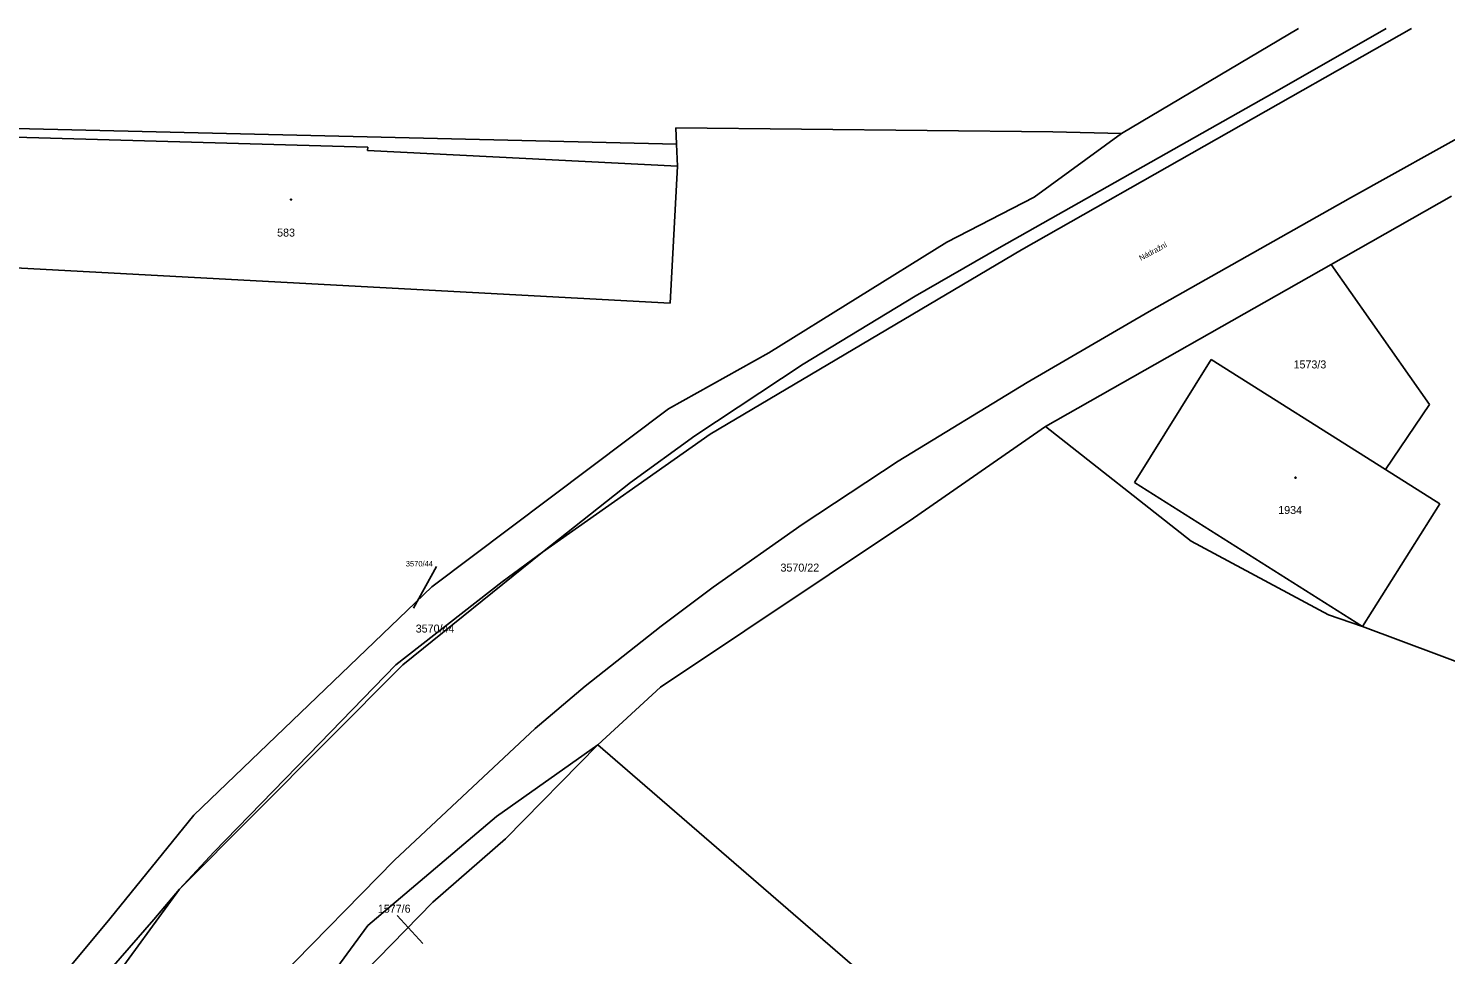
# Model space of a CAD drawing. Extents: x -866624 to -866276, y -1050208 to -1049940.
# Drawn here: x -866412 to -866323.5, y -1049998.1 to -1049940.2 of the extents above; entities that cross this region are included whole.
import ezdxf

# ---------------------------------------------------------------- set-up
doc = ezdxf.new("R2010")
doc.units = 0
for name, color, linetype in [('Default', 7, 'Continuous'), ('Hranice', 7, 'Continuous'), ('Hranice další', 7, 'Continuous'), ('Hranice-budov', 7, 'Continuous'), ('nazvy-ulic-tok', 7, 'Continuous'), ('Parcela-pozemkova', 7, 'Continuous'), ('Parcela-stavebni', 7, 'Continuous'), ('Parcelni-cisla-pomocna', 7, 'Continuous'), ('znacky-budov', 7, 'Continuous')]:
    doc.layers.add(name, color=color, linetype=linetype)

# ---------------------------------------------------------------- blocks, each defined once
blk = doc.blocks.new('s_zdena')
at = {"layer": 'Default'}
blk.add_circle((0, 0), 0.175, dxfattribs=at)
for start, end in [(0, 180), (180, 0)]:
    blk.add_arc((0, 0), 0.0875, start, end, dxfattribs=at)

msp = doc.modelspace()

# ---------------------------------------------------------------- linework, layer by layer
at = {"layer": 'Hranice'}
for p, q in [((-866325.614, -1049940.226), (-866349.97, -1049954.08)), ((-866343.73, -1049946.79), (-866332.654, -1049940.226)), ((-866333.71, -1049943.96), (-866327.177, -1049940.226)), ((-866329.42, -1049950.83), (-866310.404, -1049940.226)), ((-866333.71, -1049943.96), (-866351.36, -1049953.95)), ((-866412.83, -1049946.48), (-866371.52, -1049947.46)), ((-866371.56, -1049946.45), (-866348.02, -1049946.7)), ((-866371.56, -1049946.45), (-866371.52, -1049947.46)), ((-866343.73, -1049946.79), (-866348.02, -1049946.7)), ((-866371.52, -1049947.46), (-866371.47, -1049948.85)), ((-866349.17, -1049950.78), (-866343.73, -1049946.79)), ((-866371.47, -1049948.85), (-866371.93, -1049957.4)), ((-866354.64, -1049953.59), (-866349.17, -1049950.78)), ((-866341.99, -1049957.92), (-866329.42, -1049950.83)), ((-866323.1, -1049950.72), (-866330.63, -1049954.99)), ((-866365.76, -1049960.5), (-866354.64, -1049953.59)), ((-866349.97, -1049954.08), (-866369.43, -1049965.6)), ((-866351.36, -1049953.95), (-866356.62, -1049956.96)), ((-866416.48, -1049955), (-866371.93, -1049957.4)), ((-866330.63, -1049954.99), (-866348.47, -1049965.11)), ((-866324.48, -1049963.73), (-866330.63, -1049954.99)), ((-866363.61, -1049961.22), (-866356.62, -1049956.96)), ((-866349.61, -1049962.36), (-866341.99, -1049957.92)), ((-866372.03, -1049964), (-866365.76, -1049960.5)), ((-866342.91, -1049968.62), (-866338.12, -1049960.92)), ((-866338.12, -1049960.92), (-866327.22, -1049967.81)), ((-866363.61, -1049961.22), (-866370.38, -1049965.69)), ((-866357.67, -1049967.28), (-866349.61, -1049962.36)), ((-866372.03, -1049964), (-866386.81, -1049975.14)), ((-866324.48, -1049963.73), (-866327.22, -1049967.81)), ((-866356.72, -1049970.84), (-866348.47, -1049965.11)), ((-866339.36, -1049972.28), (-866348.47, -1049965.11)), ((-866369.43, -1049965.6), (-866379.89, -1049972.96)), ((-866374.39, -1049968.62), (-866370.38, -1049965.69)), ((-866363.67, -1049971.24), (-866357.67, -1049967.28)), ((-866327.22, -1049967.81), (-866323.84, -1049969.95)), ((-866379.89, -1049972.96), (-866374.39, -1049968.62)), ((-866328.67, -1049977.61), (-866342.91, -1049968.62)), ((-866323.84, -1049969.95), (-866328.67, -1049977.61)), ((-866356.72, -1049970.84), (-866372.52, -1049981.4)), ((-866369.23, -1049975.15), (-866363.67, -1049971.24)), ((-866330.78, -1049976.88), (-866339.36, -1049972.28)), ((-866379.89, -1049972.96), (-866388.62, -1049980)), ((-866379.89, -1049972.96), (-866382.42, -1049974.83)), ((-866382.42, -1049974.83), (-866389.05, -1049980.01)), ((-866401.67, -1049989.4), (-866386.81, -1049975.14)), ((-866372.49, -1049977.6), (-866369.23, -1049975.15)), ((-866328.67, -1049977.61), (-866330.78, -1049976.88)), ((-866377.23, -1049981.35), (-866372.49, -1049977.6)), ((-866328.67, -1049977.61), (-866316.57, -1049982.13)), ((-866388.62, -1049980), (-866402.57, -1049994.04)), ((-866394.49, -1049985.62), (-866389.05, -1049980.01)), ((-866380.36, -1049983.98), (-866377.23, -1049981.35)), ((-866376.44, -1049985.01), (-866372.52, -1049981.4)), ((-866389.15, -1049992.21), (-866380.36, -1049983.98)), ((-866394.49, -1049985.62), (-866400.43, -1049991.71)), ((-866376.44, -1049985.01), (-866382.78, -1049989.5)), ((-866382.21, -1049990.89), (-866376.44, -1049985.01)), ((-866352.98, -1050005.3), (-866376.44, -1049985.01)), ((-866406.93, -1049995.89), (-866401.67, -1049989.4)), ((-866382.78, -1049989.5), (-866390.8, -1049996.3)), ((-866382.21, -1049990.89), (-866386.74, -1049994.84)), ((-866400.43, -1049991.71), (-866402.57, -1049994.04)), ((-866396.38, -1049999.59), (-866389.15, -1049992.21)), ((-866425.65, -1050025.61), (-866402.57, -1049994.04)), ((-866402.57, -1049994.04), (-866404.17, -1049995.92)), ((-866386.74, -1049994.84), (-866393.89, -1050002.14)), ((-866406.93, -1049995.89), (-866414.35, -1050004.79)), ((-866404.17, -1049995.92), (-866408.09, -1050000.42)), ((-866390.8, -1049996.3), (-866400.72, -1050009.76))]:
    msp.add_line(p, q, dxfattribs=at)
at = {"layer": 'Hranice další'}
for p, q in [((-866412.84, -1049947.03), (-866390.81, -1049947.65)), ((-866390.81, -1049947.65), (-866390.83, -1049947.87)), ((-866371.47, -1049948.85), (-866390.83, -1049947.87))]:
    msp.add_line(p, q, dxfattribs=at)
at = {"layer": 'Hranice-budov'}
for p, q in [((-866412.84, -1049947.03), (-866390.81, -1049947.65)), ((-866390.81, -1049947.65), (-866390.83, -1049947.87)), ((-866371.47, -1049948.85), (-866390.83, -1049947.87)), ((-866371.47, -1049948.85), (-866371.93, -1049957.4)), ((-866416.48, -1049955), (-866371.93, -1049957.4)), ((-866342.91, -1049968.62), (-866338.12, -1049960.92)), ((-866338.12, -1049960.92), (-866327.22, -1049967.81)), ((-866327.22, -1049967.81), (-866323.84, -1049969.95)), ((-866328.67, -1049977.61), (-866342.91, -1049968.62)), ((-866323.84, -1049969.95), (-866328.67, -1049977.61))]:
    msp.add_line(p, q, dxfattribs=at)
at = {"layer": 'Parcelni-cisla-pomocna'}
for p, q in [((-866387.96, -1049976.46), (-866386.51, -1049973.86)), ((-866387.37, -1049997.43), (-866388.98, -1049995.67))]:
    msp.add_line(p, q, dxfattribs=at)

# ---------------------------------------------------------------- block references
at = {"layer": 'znacky-budov', "xscale": 0.2, "yscale": 0.20000000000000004}
for p in [(-866395.61, -1049950.93), (-866332.85, -1049968.31)]:
    msp.add_blockref('s_zdena', p, dxfattribs=at)

# ---------------------------------------------------------------- texts
at = {"layer": 'nazvy-ulic-tok'}
msp.add_text('Nádražní', height=0.34, rotation=28.03383, dxfattribs=at).set_placement((-866342.51, -1049954.76))
at = {"layer": 'Parcela-pozemkova'}
for s, p in [('1573/3', (-866332.974, -1049961.483)), ('3570/22', (-866365.027, -1049974.183)), ('3570/44', (-866387.817, -1049977.993)), ('1577/6', (-866390.184, -1049995.503))]:
    msp.add_text(s, height=0.5, dxfattribs=at).set_placement(p)
at = {"layer": 'Parcela-stavebni'}
for s, p in [('583', (-866396.477, -1049953.243)), ('1934', (-866333.929, -1049970.583))]:
    msp.add_text(s, height=0.5, dxfattribs=at).set_placement(p)
at = {"layer": 'Parcelni-cisla-pomocna'}
msp.add_text('3570/44', height=0.34, dxfattribs=at).set_placement((-866388.437, -1049973.86))

doc.saveas('drawing.dxf')
